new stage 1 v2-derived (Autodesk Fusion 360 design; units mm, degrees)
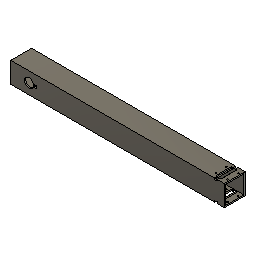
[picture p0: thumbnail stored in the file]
parameter "d495" = 0
parameter "d496" = 0
parameter "d497" = 0
parameter "d498" = 0
sketch "Sketch1" plane through (0, 0, 0) normal (1, 0, 0) x axis (0, 0, -1)
  line L1 (50.8, 0) -> (0, 0)
  line L2 (50.8, 50.8) -> (50.8, 0)
  line L3 (0, 50.8) -> (50.8, 50.8)
  line L4 (0, 0) -> (0, 50.8)
  line L5 (47.5234, 3.2766) -> (3.2766, 3.2766)
  line L6 (47.5234, 47.5234) -> (47.5234, 3.2766)
  line L7 (3.2766, 47.5234) -> (47.5234, 47.5234)
  line L8 (3.2766, 3.2766) -> (3.2766, 47.5234)
  point P1 (0, 0)
  point P2 (0, 0)
  point P3 (50.8, 0)
  point P5 (0, 50.8)
  horizontal L1
  vertical L2
  horizontal L3
  vertical L4
  coincident P1 P2
  dimension "d1_1" distance P2 P3 = 50.8
  dimension "d2_1" distance P2 P5 = 50.8
  dimension "d3_1" = -3.2766
  dimension "d158" OffsetX = 0
  dimension "d159" OffsetY = 0
  dimension "d160" OffsetZ = 0
  dimension "d161" AngleZ = 0
  dimension "d215" OffsetX = 0
  dimension "d216" OffsetY = 0
  dimension "d217" OffsetZ = 0
  dimension "d218" AngleZ = 0
  dimension "d223" OffsetX = 0
  dimension "d224" OffsetY = 0
  dimension "d225" OffsetZ = 0
  dimension "d226" AngleZ = 0
  dimension "d231" OffsetX = 0
  dimension "d232" OffsetY = 0
  dimension "d233" OffsetZ = 0
  dimension "d234" AngleZ = 0
  dimension "d239" OffsetX = 0
  dimension "d240" OffsetY = 0
  dimension "d241" OffsetZ = 0
  dimension "d242" AngleZ = 0
  dimension "d339" OffsetX = 0
  dimension "d340" OffsetY = 0
  dimension "d341" OffsetZ = 0
  dimension "d342" AngleZ = 0
  dimension "d347" OffsetX = 0
  dimension "d348" OffsetY = 0
  dimension "d349" OffsetZ = 0
  dimension "d350" AngleZ = 0
  dimension "d355" OffsetX = 0
  dimension "d356" OffsetY = 0
  dimension "d357" OffsetZ = 0
  dimension "d358" AngleZ = 0
  dimension "d363" OffsetX = 0
  dimension "d364" OffsetY = 0
  dimension "d365" OffsetZ = 0
  dimension "d366" AngleZ = 0
  dimension "d376" OffsetX = 0
  dimension "d377" OffsetY = 0
  dimension "d378" OffsetZ = 0
  dimension "d379" AngleZ = 0
  dimension "d384" OffsetX = 0
  dimension "d385" OffsetY = 0
  dimension "d386" OffsetZ = 0
  dimension "d387" AngleZ = 0
  dimension "d392" OffsetX = 0
  dimension "d393" OffsetY = 0
  dimension "d394" OffsetZ = 0
  dimension "d395" AngleZ = 0
  dimension "d479" OffsetX = 0
  dimension "d480" OffsetY = 0
  dimension "d481" OffsetZ = 0
  dimension "d482" AngleZ = 0
  dimension "d487" OffsetX = 0
  dimension "d488" OffsetY = 0
  dimension "d489" OffsetZ = 0
  dimension "d490" AngleZ = 0
extrude "Extrude1" new body sketch "Sketch1" along a picked direction blind 520.7 named "d4_1"
hole "Hole2" HoleDepth 101.6 HoleDiameter 22.225 TipAngle 118 RefDim1 44.45 (= "1 in + ( 3 / 4 ) * 1 in") RefDim2 25.4
sketch "Sketch2" plane through (0, 0, 0) normal (0, 0, 1) x axis (1, 0, 0)
  line L1 (0, 50.8) -> (520.7, 50.8)
  line L2 (0, 0) -> (0, 50.8)
  line L3 (520.7, 0) -> (0, 0)
  line L4 (496.7478, 47.498) -> (503.3518, 47.498)
  line L5 (496.7478, 54.102) -> (496.7478, 47.498)
  line L6 (503.3518, 54.102) -> (496.7478, 54.102)
  line L7 (503.3518, 47.498) -> (503.3518, 54.102)
  line L8 (496.7478, 54.102) -> (503.3518, 47.498)
  line L9 (503.3518, 54.102) -> (496.7478, 47.498)
  line L10 (496.7478, 3.302) -> (503.3518, 3.302)
  line L11 (496.7478, -3.302) -> (496.7478, 3.302)
  line L12 (503.3518, -3.302) -> (496.7478, -3.302)
  line L13 (503.3518, 3.302) -> (503.3518, -3.302)
  line L14 (496.7478, -3.302) -> (503.3518, 3.302)
  line L15 (503.3518, -3.302) -> (496.7478, 3.302)
  line L16 (520.7, 50.8) -> (520.7, 0)
  line L17 (520.7, 50.8) -> (520.7, 0)
  circle C1 centre (44.45, 25.4) radius 11.1125
  circle C2 centre (500.0498, 50.8) radius 3.302
  circle C3 centre (500.0498, 0) radius 3.302
  point P7 (500.0498, 50.8)
  point P8 (500.0498, 0)
  point P13 (500.0498, 50.8)
  point P18 (500.0498, 0)
  point P10 (496.7478, 47.498)
  point P11 (496.7478, 54.102)
  point P12 (503.3518, 54.102)
  point P16 (496.7478, -3.302)
  point P17 (503.3518, -3.302)
  point P15 (496.7478, 3.302)
  coincident L1 P7
  coincident L3 P8
  perpendicular L4 L5
  parallel L4 L6
  parallel L5 L7
  horizontal L4
  coincident L8 P13
  coincident L9 P13
  coincident P7 P13
  perpendicular L10 L11
  parallel L10 L12
  parallel L11 L13
  horizontal L10
  coincident L14 P18
  coincident L15 P18
  coincident P8 P18
  dimension "d412" diameter C2 = 6.604
  dimension "d413" diameter C3 = 6.604
  dimension "d428" distance P10 P11 = 6.604
  dimension "d429" distance P11 P12 = 6.604
  dimension "d430" distance P16 P17 = 6.604
  dimension "d431" distance P15 P16 = 6.604
  dimension "d540" distance L13 L17 = 17.3482
  dimension "d541" distance L7 L17 = 17.3482
extrude "Extrude3" cut sketch "Sketch2" profile of L1 L3 C2 C3 L4 L5 L7 L10 L11 L13 along a picked direction blind -50.8
sketch "Sketch3" plane through (0, 0, 0) normal (0, -1, 0) x axis (1, 0, 0)
  line L1 (520.7, -50.8) -> (503.3518, -50.8)
  line L2 (503.3518, 0) -> (520.7, 0)
  line L3 (493.1918, -6.35) -> (506.9078, -6.35)
  line L4 (493.1918, -19.05) -> (493.1918, -6.35)
  line L5 (506.9078, -19.05) -> (493.1918, -19.05)
  line L6 (506.9078, -6.35) -> (506.9078, -19.05)
  line L7 (493.1918, -19.05) -> (506.9078, -19.05)
  line L8 (493.1918, -44.45) -> (493.1918, -19.05)
  line L9 (506.9078, -44.45) -> (493.1918, -44.45)
  line L10 (506.9078, -19.05) -> (506.9078, -44.45)
  line L11 (503.3518, -50.8) -> (503.3518, 0)
  line L12 (496.7478, 0) -> (496.7478, -50.8)
  line L13 (520.7, 0) -> (520.7, -50.8)
  line L14 (496.7478, 0) -> (496.7478, -50.8)
  line L15 (0, 0) -> (496.7478, 0)
  line L16 (0, -50.8) -> (0, 0)
  line L17 (496.7478, -50.8) -> (0, -50.8)
  point P6 (506.9078, -6.35)
  point P9 (506.9078, -19.05)
  point P7 (493.1918, -6.35)
  point P10 (506.9078, -19.05)
  point P11 (493.1918, -19.05)
  point P13 (506.9078, -44.45)
  horizontal L3
  vertical L4
  horizontal L5
  vertical L6
  horizontal L7
  vertical L8
  horizontal L9
  vertical L10
  dimension "d418" distance P6 P9 = 12.7
  dimension "d419" distance P6 P7 = 13.716
  dimension "d420" distance P10 P11 = 13.716
  dimension "d421" distance P10 P13 = 25.4
  dimension "d422" distance L1 L9 = 6.35
  dimension "d423" distance L2 L3 = 6.35
  dimension "d432" distance L4 L12 = 3.556
  dimension "d433" distance L8 L12 = 3.556
extrude "Extrude4" cut sketch "Sketch3" profile of L3 L4 L5 L6 L7 L8 L9 L10 L11 L12 against normal blind 3.175
extrude "Extrude5" sketch "Sketch3" profile of L3 L4 L5 L6 L7 L8 L9 L10 L11 L12 blind 3.175
fillet "Fillet1" radius 1.5875 1.5875
sketch "Sketch4" plane through (0, 50.8, 0) normal (0, 1, 0) x axis (-1, 0, 0)
  line L1 (-469.3793, -6.35) -> (-469.7603, -6.35)
  line L2 (-467.7918, -42.8625) -> (-467.7918, -7.9375)
  line L3 (-469.7603, -44.45) -> (-469.3793, -44.45)
  line L4 (-471.3478, -50.8) -> (-471.3478, -46.0375)
  line L5 (0, -50.8) -> (-471.3478, -50.8)
  line L6 (0, 0) -> (0, -50.8)
  line L7 (-471.3478, 0) -> (0, 0)
  line L8 (-471.3478, -4.7625) -> (-471.3478, 0)
  line L9 (-520.7, -50.8) -> (-477.9518, -50.8)
  line L10 (-503.3518, 0) -> (-503.3518, -4.7625)
  line L11 (-520.7, 0) -> (-503.3518, 0)
  line L12 (-520.7, -50.8) -> (-520.7, 0)
  line L13 (-503.3518, -50.8) -> (-520.7, -50.8)
  line L14 (-503.3518, -46.0375) -> (-503.3518, -50.8)
  line L15 (-505.3203, -44.45) -> (-504.9393, -44.45)
  line L16 (-506.9078, -7.9375) -> (-506.9078, -42.8625)
  line L17 (-504.9393, -6.35) -> (-505.3203, -6.35)
  arc A1 centre (-469.7603, -4.7625) radius 1.5875 clockwise from (-469.7603, -6.35) to (-471.3478, -4.7625)
  arc A2 centre (-469.3793, -7.9375) radius 1.5875 clockwise from (-469.3793, -6.35) to (-467.7918, -7.9375)
  arc A3 centre (-469.7603, -46.0375) radius 1.5875 clockwise from (-471.3478, -46.0375) to (-469.7603, -44.45)
  circle C1 centre (-515.9248, -38.1) radius 2.5527
  circle C2 centre (-487.3498, -38.1) radius 2.5527
  circle C3 centre (-515.9248, -12.7) radius 2.5527
  circle C4 centre (-487.3498, -12.7) radius 2.5527
  arc A4 centre (-469.3793, -42.8625) radius 1.5875 clockwise from (-467.7918, -42.8625) to (-469.3793, -44.45)
  arc A5 centre (-504.9393, -4.7625) radius 1.5875 clockwise from (-503.3518, -4.7625) to (-504.9393, -6.35)
  arc A6 centre (-504.9393, -46.0375) radius 1.5875 clockwise from (-504.9393, -44.45) to (-503.3518, -46.0375)
  arc A7 centre (-505.3203, -42.8625) radius 1.5875 clockwise from (-505.3203, -44.45) to (-506.9078, -42.8625)
  arc A8 centre (-505.3203, -7.9375) radius 1.5875 clockwise from (-506.9078, -7.9375) to (-505.3203, -6.35)
  point P17 (-515.9248, -38.1)
  dimension "d441" diameter C1 = 5.1054
  dimension "d443" distance P17 L9 = 12.7
  dimension "d539" distance P17 L12 = 4.7752
  dimension "d446" R-Pattern1-uDistance = 28.575
  dimension "d447" R-Pattern1-vDistance = 25.4
hole "Hole3" HoleDepth 50.8 HoleDiameter 3.429 TipAngle 118
sketch "Sketch5" plane through (0, 0, 0) normal (0, 0, 1) x axis (1, 0, 0)
  line L1 (503.3518, 47.498) -> (503.3518, 50.8)
  line L2 (496.7478, 47.498) -> (503.3518, 47.498)
  line L3 (496.7478, 50.8) -> (496.7478, 47.498)
  line L4 (0, 50.8) -> (496.7478, 50.8)
  line L5 (0, 0) -> (0, 50.8)
  line L6 (496.7478, 0) -> (0, 0)
  line L7 (496.7478, 3.302) -> (496.7478, 0)
  line L8 (503.3518, 3.302) -> (496.7478, 3.302)
  line L9 (503.3518, 0) -> (503.3518, 3.302)
  line L10 (520.7, 0) -> (503.3518, 0)
  line L11 (520.7, 50.8) -> (520.7, 0)
  line L12 (503.3518, 50.8) -> (520.7, 50.8)
  circle C1 centre (44.45, 25.4) radius 11.1125
  circle C2 centre (60.325, 25.4) radius 3.3782
  point P14 (44.45, 25.4)
  point P15 (60.325, 25.4)
  dimension "d542" diameter C2 = 6.7564
  dimension "d543" distance P14 P15 = 15.875
  dimension "d544" distance L4 P15 = 25.4
hole "Hole4" HoleDepth 38.1 HoleDiameter 6.7564 TipAngle 118
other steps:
thread "Thread1"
